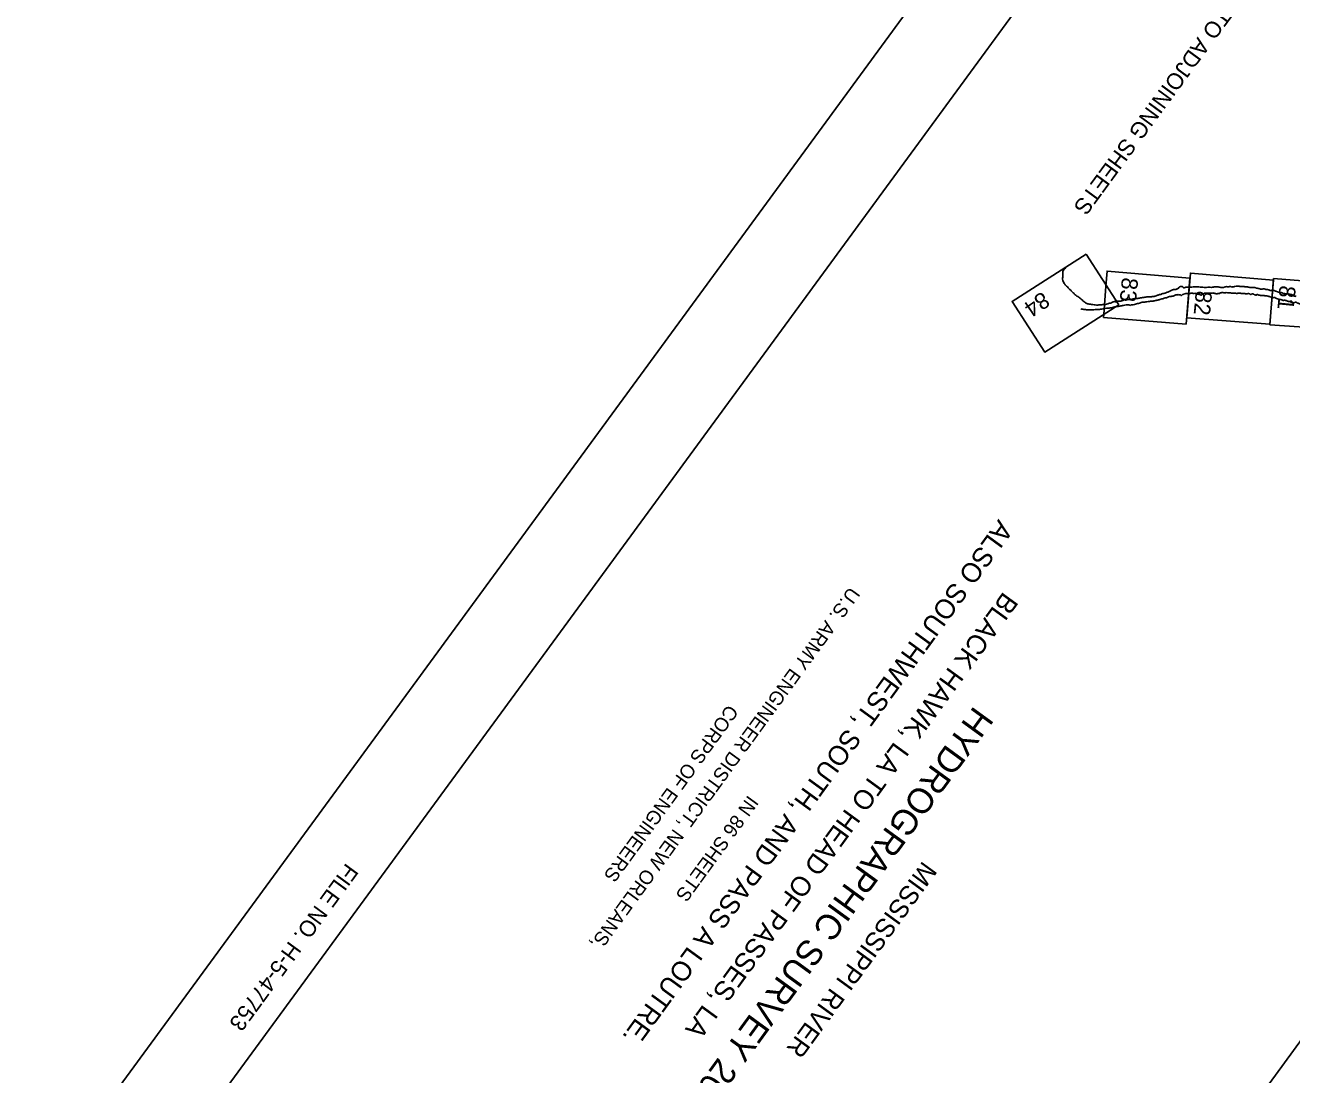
# Model space of a CAD drawing. Extents: x 3905714 to 3926767, y 183354 to 205755.
# Drawn here: x 3905949 to 3910493, y 191234 to 194998 of the extents above; entities that cross this region are included whole.
import ezdxf

# ---------------------------------------------------------------- set-up
doc = ezdxf.new("R2010")
doc.units = 0
for name, color, linetype in [('G-ANNO-NPLT', 7, 'Continuous'), ('V-ANNO-NPLT', 7, 'Continuous'), ('V-ANNO-SYMB', 7, 'Continuous'), ('V-ANNO-TEXT', 7, 'Continuous'), ('V-GRID-FRAM', 7, 'Continuous')]:
    doc.layers.add(name, color=color, linetype=linetype)

msp = doc.modelspace()

# ---------------------------------------------------------------- linework, layer by layer
at = {"layer": 'G-ANNO-NPLT'}
msp.add_lwpolyline([(3916784.5, 205519.9), (3905949.4, 190731), (3915696.7, 183589.7), (3926531.8, 198378.7)], close=True, dxfattribs=at)
at = {"layer": 'V-ANNO-NPLT'}
for points in [[(3909755, 194177.2), (3909489.6, 194007.8), (3909606.9, 193826.2), (3909872.4, 193995.6)], [(3909872.4, 193995.6), (3909755, 194177.2)], [(3910127.9, 194091.7), (3909830.8, 194116.7), (3909826.7, 194063)], [(3910116.2, 193948.7), (3910129.4, 194109.6), (3910427.4, 194084)], [(3909826.7, 194063), (3909819.1, 193961.5)], [(3910127.9, 194091.7), (3910114.4, 193926.8)], [(3910427.9, 194090.6), (3910414.8, 193924.5), (3910712.8, 193903.4)], [(3910415, 193926.7), (3910427.4, 194084)], [(3910427.9, 194090.6), (3910725.4, 194066.7)], [(3909819.1, 193961.5), (3909818.2, 193950.7), (3910114.4, 193926.8)], [(3910415, 193926.7), (3910116.2, 193948.7)]]:
    msp.add_lwpolyline(points, dxfattribs=at)
for points in [[(3909697.5, 194050.1), (3909690.9, 194057.1), (3909685.3, 194062.5), (3909680.6, 194067.2), (3909677.2, 194072.4), (3909673.6, 194079.3), (3909671, 194087.9), (3909671.5, 194095.2), (3909671.6, 194101.4), (3909671.5, 194108.8), (3909672.2, 194114.9), (3909674.6, 194120.7), (3909679.4, 194126.2), (3909682.6, 194128.6)], [(3910097.4, 194061), (3910094.8, 194062), (3910092.9, 194061.5), (3910090.2, 194060.1), (3910085.4, 194054.6), (3910082.4, 194052.7), (3910077.9, 194051.4), (3910072.2, 194050.6), (3910066.8, 194049.7), (3910063.3, 194048.5), (3910058.4, 194046.6), (3910054, 194044.2), (3910050.8, 194042.9), (3910046.6, 194040.7), (3910042, 194038.8), (3910038.1, 194037.4), (3910034.9, 194037), (3910027.4, 194035), (3910025.6, 194033.9), (3910021.9, 194033.2), (3910017.7, 194032.3), (3910013.8, 194030.9), (3910009.5, 194029), (3910006.5, 194027.9), (3910004, 194027.2), (3910001.3, 194026.5), (3910000.4, 194026.2)], [(3910192, 194058.7), (3910183.2, 194058.4), (3910174, 194058.8), (3910164.7, 194059.5), (3910154, 194060.1), (3910147.7, 194060.1), (3910138.9, 194059.8), (3910129.3, 194059.2), (3910125, 194059.4), (3910118.7, 194059.1), (3910113.4, 194058.7), (3910107.7, 194057), (3910102.5, 194059), (3910101.2, 194061), (3910098.8, 194061.2), (3910097.4, 194061)], [(3910250, 194058.2), (3910249.3, 194057.8), (3910246.1, 194057.4), (3910242, 194057.9), (3910238.2, 194058.3), (3910232.9, 194059.2), (3910225.2, 194060.3), (3910217.9, 194059.9), (3910215.1, 194060.1), (3910209.3, 194059.1), (3910200.4, 194058.6), (3910197.7, 194058.8), (3910194.3, 194058.9), (3910192, 194058.7)], [(3910260.2, 194060.9), (3910258.1, 194061.1), (3910255.3, 194060.7), (3910252.6, 194059.9), (3910250.9, 194059), (3910250, 194058.2)], [(3910309.6, 194061.7), (3910308.1, 194061.7), (3910304.7, 194062.6), (3910301.2, 194063.1), (3910297.3, 194062.9), (3910289.5, 194061.9), (3910284.9, 194060.3), (3910280.4, 194059.9), (3910276.8, 194060.1), (3910274.9, 194061.3), (3910269.7, 194061.1), (3910264.9, 194060.3), (3910261.6, 194060.6), (3910260.2, 194060.9)], [(3910323.1, 194061.2), (3910319.9, 194061.6), (3910317, 194061.8), (3910313.3, 194061.9), (3910311, 194062.2), (3910309.6, 194061.7)], [(3910361.8, 194057.4), (3910360.5, 194058), (3910358.9, 194058.3), (3910354.7, 194058.3), (3910350.8, 194058.4), (3910346.5, 194058.2), (3910342.4, 194057.9), (3910336.4, 194059.6), (3910331.5, 194059.8), (3910327.5, 194060), (3910324.8, 194060.5), (3910323.1, 194061.2)], [(3910370, 194055.2), (3910368.5, 194055.2), (3910366.7, 194055.6), (3910364.2, 194056.2), (3910363.3, 194056.6), (3910361.8, 194057.4)], [(3910437.2, 194044.4), (3910433.8, 194045.4), (3910430.4, 194046.7), (3910425.9, 194046.7), (3910420, 194046.8), (3910416.8, 194047.2), (3910413.1, 194048.5), (3910409.1, 194049.6), (3910405.6, 194050.7), (3910402.1, 194050.8), (3910399.9, 194051.2), (3910396.4, 194052.4), (3910394.4, 194053.6), (3910391.6, 194053.2), (3910387.7, 194052.3), (3910382.9, 194052.5), (3910379.2, 194052.8), (3910376.4, 194054), (3910372.7, 194054.6), (3910370, 194055.2)], [(3909750.3, 194005.6), (3909737.6, 194015.9), (3909726.2, 194025.3), (3909718, 194029.9), (3909710.9, 194037.2), (3909703.3, 194044.4), (3909700.2, 194048.2), (3909697.5, 194050.1)], [(3909846.5, 194003.3), (3909839.2, 194001.2), (3909832.9, 193999.3), (3909825.1, 193997.3), (3909817.3, 193997.6), (3909812.3, 193996.2), (3909801.6, 193995.3), (3909792.6, 193995), (3909783.9, 193996), (3909774.9, 193997.2), (3909766.5, 193998.4), (3909759.9, 194000), (3909755.5, 194001.7), (3909751.2, 194004.9), (3909750.3, 194005.6)], [(3909907.3, 194015.4), (3909904.2, 194014.8), (3909901.1, 194013.7), (3909898.5, 194013.1), (3909895.4, 194013.1), (3909892.6, 194013.5), (3909887.3, 194011.8), (3909884.2, 194010.6), (3909879.4, 194009.5), (3909875.4, 194008.9), (3909870.7, 194008.5), (3909867.2, 194008.6), (3909863.9, 194007.1), (3909860.3, 194007.1), (3909856.8, 194007.2), (3909852.5, 194006.1), (3909848.2, 194004.5), (3909846.5, 194003.3)], [(3910000.4, 194026.2), (3909992.4, 194025.3), (3909987.4, 194025), (3909981.1, 194025), (3909965.8, 194022.8), (3909950.3, 194020.7), (3909937.8, 194018.4), (3909928.5, 194017.9), (3909920.9, 194016.1), (3909913.8, 194014.8), (3909907.3, 194015.4)], [(3910000.8, 194010.4), (3909995.6, 194009), (3909982.9, 194008.2), (3909972.9, 194006.3), (3909959.5, 194005.4), (3909947.2, 194002.1), (3909932.6, 193998.3), (3909924.8, 193996.4), (3909919.7, 193995.9), (3909914.9, 193993.8), (3909914.8, 193993.4)], [(3910097.8, 194029.5), (3910097, 194029.5), (3910095.6, 194029.7), (3910094.1, 194031.5), (3910089.8, 194032.2), (3910085.5, 194032.3), (3910080.4, 194031.8), (3910075.4, 194030.2), (3910069.8, 194027.8), (3910065.2, 194027.2), (3910060.6, 194026.2), (3910055.9, 194025.4), (3910051.8, 194024.7), (3910048.1, 194023.1), (3910043.3, 194021.4), (3910035.8, 194019.5), (3910031.2, 194017.9), (3910027.2, 194016.9), (3910020.4, 194015.4), (3910015.3, 194013.3), (3910009.6, 194012.5), (3910003.4, 194010.9), (3910000.7, 194010.4)], [(3910173.8, 194035.2), (3910170.8, 194033.4), (3910170.3, 194031.9), (3910169.2, 194030.5), (3910167.4, 194030.6), (3910164.5, 194031.8), (3910161.1, 194032.8), (3910155.7, 194034.4), (3910150.6, 194036.1), (3910145.8, 194037.2), (3910139, 194037), (3910135.8, 194037.8), (3910130.7, 194037.3), (3910127.7, 194036.7), (3910122.4, 194036.4), (3910117.4, 194036.1), (3910113.3, 194036.6), (3910105.1, 194033.7), (3910101.7, 194032.5), (3910097.8, 194029.5)], [(3910233.1, 194035.9), (3910230.8, 194036.1), (3910227.9, 194036.1), (3910223.8, 194035.2), (3910219.1, 194036.2), (3910215, 194037.4), (3910210, 194038.3), (3910204.7, 194038), (3910199, 194037.6), (3910195, 194037.7), (3910187.9, 194038), (3910182.5, 194038), (3910178.5, 194037.3), (3910176.6, 194035.3), (3910173.8, 194035.2)], [(3910291.8, 194037.2), (3910285.6, 194037.9), (3910280.2, 194037.9), (3910274, 194038.5), (3910267.7, 194038.9), (3910258.2, 194039.5), (3910252.4, 194038.9), (3910249.2, 194038.8), (3910243.4, 194040.3), (3910240.1, 194039.3), (3910235.3, 194037.3), (3910234.3, 194036.8), (3910232.3, 194035.4)], [(3910339.2, 194036.2), (3910335.3, 194036), (3910332.7, 194035.5), (3910327.1, 194035.6), (3910322.6, 194036.5), (3910316.9, 194036.8), (3910313.4, 194036.9), (3910309.2, 194037.2), (3910305.3, 194037.4), (3910302.7, 194037.7), (3910299.7, 194037.5), (3910295.8, 194036.6), (3910293.3, 194037), (3910291.8, 194037.2)], [(3910423.4, 194022), (3910420.6, 194023.8), (3910418.8, 194023.9), (3910413.4, 194025.2), (3910408.8, 194026.7), (3910404.4, 194027.9), (3910400, 194028.1), (3910396.9, 194028.5), (3910391.1, 194029.2), (3910385.8, 194029.4), (3910382.4, 194029.5), (3910378.9, 194030.2), (3910375.4, 194031), (3910369.9, 194032.6), (3910367.3, 194031.7), (3910366.2, 194031), (3910362, 194031.4), (3910359.2, 194031.9), (3910356.8, 194033.7), (3910354, 194035), (3910349.7, 194034.7), (3910347.5, 194033.2), (3910346.4, 194032.5), (3910343.8, 194034.1), (3910342.1, 194035.2), (3910340.4, 194035.8), (3910339.1, 194036.2)], [(3910483.3, 194008.2), (3910479.1, 194008.7), (3910475.1, 194010.2), (3910470.8, 194011.6), (3910466.4, 194012.1), (3910461.8, 194011.8), (3910459.2, 194013.4), (3910453.5, 194014.6), (3910449.6, 194015.4), (3910444.8, 194016.5), (3910441.5, 194017.7), (3910436.2, 194020.2), (3910433.1, 194021.6), (3910430.4, 194022.7), (3910428, 194022), (3910425.8, 194021.1), (3910424.1, 194021.8), (3910423.4, 194022)], [(3910509.2, 194026.3), (3910505.2, 194026.8), (3910501.1, 194028.1), (3910498.4, 194029.1), (3910494.8, 194031.9), (3910490.2, 194032.9), (3910486.7, 194033.7), (3910484.4, 194034.1), (3910480.6, 194034.8), (3910474.6, 194034.9), (3910471.5, 194035.4), (3910468.2, 194036), (3910464.7, 194036.5), (3910460.8, 194037.5), (3910458, 194039.3), (3910454.6, 194040.3), (3910451.5, 194040.8), (3910448.2, 194041.4), (3910445.5, 194041.6), (3910442.7, 194042.1), (3910439.3, 194043.1), (3910437.7, 194044.3), (3910437.2, 194044.4)], [(3910572.9, 194001.7), (3910571.1, 194000.9), (3910570.5, 194000.1), (3910566.1, 193999.6), (3910561.5, 193999.4), (3910554.5, 193999.3), (3910548.4, 193998.5), (3910539.8, 193998.8), (3910536.7, 193998.9), (3910535.1, 193998.9), (3910534.5, 193998.1), (3910534.4, 193997.5), (3910531.7, 193997.3), (3910528, 193997.9), (3910523.9, 193999.5), (3910520.4, 193999.9), (3910516.4, 194001.7), (3910512.4, 194002.8), (3910510.6, 194004.5), (3910507.3, 194005.2), (3910504.3, 194004.6), (3910501.9, 194003.5), (3910499.2, 194003.4), (3910495, 194004.4), (3910491, 194005.8), (3910487.4, 194007.3), (3910484.6, 194007.9), (3910483.3, 194008.2)], [(3909820.3, 193982.4), (3909803.1, 193979.3), (3909792.2, 193978.9), (3909773.5, 193977.6), (3909765, 193977.4), (3909756.8, 193978.3), (3909743.5, 193980.1), (3909736.9, 193981.2)], [(3909914.9, 193993.6), (3909908.4, 193995.3), (3909904.6, 193995.6), (3909898.6, 193995.7), (3909889.5, 193993.8), (3909876.8, 193991.1), (3909867, 193989.7), (3909861.3, 193989.2), (3909850.4, 193986.5), (3909841.6, 193984.8), (3909828.2, 193983.5), (3909820.3, 193982.4)]]:
    msp.add_spline(points, degree=3, dxfattribs=at)
at = {"layer": 'V-ANNO-SYMB'}
msp.add_lwpolyline([(3916223.9, 204226), (3906447.8, 190882.4), (3915690.8, 184110.5), (3925467, 197454.1), (3916223.9, 204226)], dxfattribs=at)
at = {"layer": 'V-GRID-FRAM'}
msp.add_lwpolyline([(3924287.8, 196971.1), (3915521.4, 185005.6), (3909313.3, 189695.8), (3918205.9, 201877.9), (3924287.8, 196971.1)], dxfattribs=at)

# ---------------------------------------------------------------- texts
at = {"layer": 'V-ANNO-NPLT'}
for s, height, rotation, p in [('INDEX TO ADJOINING SHEETS', 58.33, 233.7718, (3910386.5, 195273.4)), ('83', 58.5, 264.4837, (3909884.3, 194095.7)), ('81', 58.5, 264.4837, (3910449.8, 194067.2)), ('84', 58.5, 214.4837, (3909598.4, 194045.8)), ('82', 58.5, 264.4837, (3910149.5, 194048))]:
    msp.add_text(s, height=height, rotation=rotation, dxfattribs=at).set_placement(p)
at = {"layer": 'V-ANNO-TEXT'}
for s, height, rotation, p in [('ALSO SOUTHWEST, SOUTH, AND PASS A LOUTRE.', 70, 233.9476, (3909441.4, 193228.8)), ('U.S. ARMY ENGINEER DISTRICT, NEW ORLEANS,', 50, 233.9476, (3908907, 192987.2)), ('BLACK HAWK, LA TO HEAD OF PASSES, LA', 70, 233.9476, (3909459.2, 192969.7)), ('CORPS OF ENGINEERS', 50, 233.9476, (3908470.8, 192565.1)), ('HYDROGRAPHIC SURVEY 2013', 90.85, 233.9476, (3909354.3, 192560.4)), ('IN 86 SHEETS', 50, 233.9476, (3908543.1, 192239.8)), ('FILE NO. H-5-47753', 58.33, 233.7718, (3907101, 191996.5)), ('MISSISSIPPI RIVER', 67.5, 233.9476, (3909169.9, 192003.8))]:
    msp.add_text(s, height=height, rotation=rotation, dxfattribs=at).set_placement(p)

doc.saveas('drawing.dxf')
